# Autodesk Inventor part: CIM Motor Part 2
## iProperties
Created: 2010-01
Part Number: CIM Motor Part 2
Document SubType Name: Modeling
Designer: cmcfadden
Density: 1 g/cm^3
Author: cmcfadden
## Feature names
1. Extrusion1
